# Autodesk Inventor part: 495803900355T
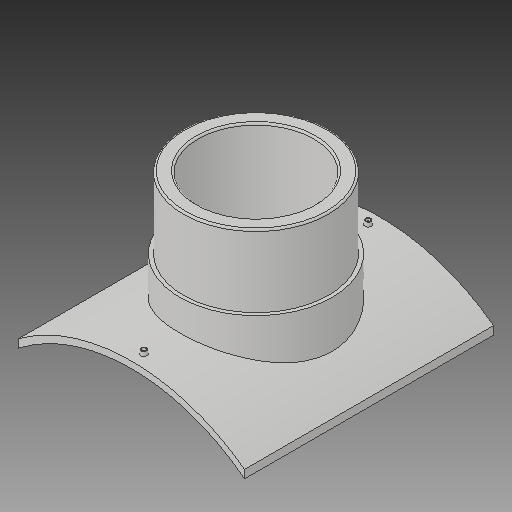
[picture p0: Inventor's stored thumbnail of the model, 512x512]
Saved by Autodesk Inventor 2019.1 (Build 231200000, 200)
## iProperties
Created: 2017-10
Part Number: 495803900355T
Material: Generic
Description: PLASSON BRANCH SADDLE  900x355
Document SubType Name: Modeling
Designer: KIM
Mass: 2754.05 g
Surface Area: 3037.44 cm^2
Volume: 2754.05 cm^3
Density: 1 g/cm^3
Appearance: Default
Author: KIM
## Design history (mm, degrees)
derived "495803.ipt"
feature "Solid1::495803.ipt"
tag "TaggingFeature1"
body "Solid1"
other parameters: "d1" = 16, "d2" = 554, "d4" = 0, "d12" = 475.6, "d13" = 14, "d14" = 274.5, "d16" = 5 deg, "d18" = 4, "d19" = 14, "d20" = 0, "d21" = 3, "d22" = 0, "d23" = 718, "d24" = 372.75, "d25" = 16, "d26" = 284, "d28" = 0, "d29" = 9.6, "d31" = 0, "d32" = 126, "d33" = 0, "d34" = 9, "d36" = 355, "d37" = 176.4, "d38" = 0, "d39" = 4.5, "d_1" = 355, "B_" = 554, "H_" = 252, "x_" = 16, "D_" = 16
